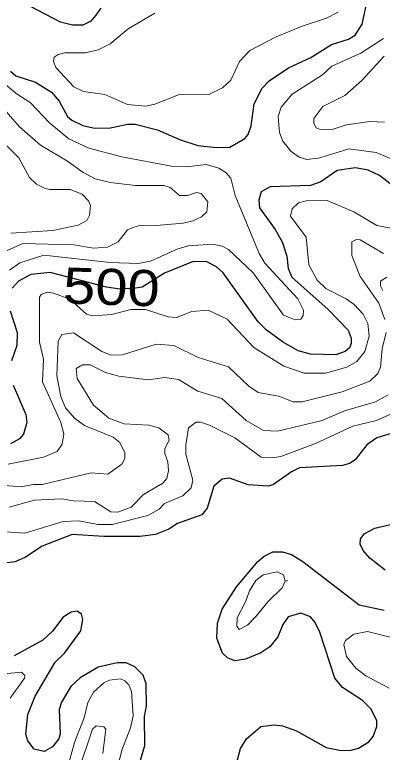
# Model space of a CAD drawing. Extents: x 577 to 602.9, y 7483.8 to 7511.6.
# Drawn here: x 598.664 to 599.479, y 7491.079 to 7492.716 of the extents above; entities that cross this region are included whole.
import ezdxf
from ezdxf.enums import TextEntityAlignment as Align

# ---------------------------------------------------------------- set-up
doc = ezdxf.new("R2010")
doc.units = 0
doc.header["$LTSCALE"] = 0.032
doc.layers.add('1', color=7, linetype='Continuous', lineweight=25)
doc.layers.add('2', color=7, linetype='Continuous', lineweight=13)
doc.layers.add('61', color=7, linetype='Continuous')

msp = doc.modelspace()

# ---------------------------------------------------------------- linework, layer by layer
at = {"layer": '1'}
for points in [[(598.6545, 7492.5903), (598.6664, 7492.58), (598.7102, 7492.5657), (598.7459, 7492.5434), (598.7626, 7492.5235), (598.7809, 7492.4901), (598.7905, 7492.4814), (598.8151, 7492.4695), (598.8382, 7492.4647), (598.8724, 7492.4639), (598.9145, 7492.4726), (598.9312, 7492.4726), (598.9805, 7492.4599), (599.0298, 7492.4384), (599.0704, 7492.4257), (599.1109, 7492.421), (599.1411, 7492.4217), (599.1745, 7492.4408), (599.1817, 7492.4496), (599.1888, 7492.4687), (599.1952, 7492.518), (599.2127, 7492.553), (599.2286, 7492.5689), (599.2715, 7492.5975), (599.3208, 7492.6205), (599.367, 7492.6492), (599.4043, 7492.6611), (599.4194, 7492.6706), (599.4346, 7492.6945), (599.4473, 7492.7533)], [(598.8549, 7492.7303), (598.8437, 7492.7144), (598.8326, 7492.7016), (598.8151, 7492.6921), (598.7921, 7492.6921), (598.7658, 7492.6993), (598.699, 7492.7335)], [(599.4735, 7492.3589), (599.4481, 7492.3709), (599.4202, 7492.3756), (599.3797, 7492.3701), (599.3431, 7492.3446), (599.3201, 7492.3367), (599.231, 7492.3335), (599.2111, 7492.3223), (599.2055, 7492.3041), (599.2071, 7492.2874), (599.2421, 7492.2389), (599.2572, 7492.2118), (599.2676, 7492.18), (599.2707, 7492.1522), (599.2787, 7492.1331), (599.3598, 7492.0615), (599.4035, 7492.0154), (599.4107, 7491.9979), (599.4107, 7491.986), (599.4067, 7491.9764), (599.3972, 7491.9685), (599.3765, 7491.9613), (599.3201, 7491.9621), (599.293, 7491.9701), (599.258, 7491.99), (599.2222, 7492.0162), (599.204, 7492.0345), (599.1268, 7492.1426), (599.1117, 7492.1562), (599.0902, 7492.1673), (599.06, 7492.1681), (598.9964, 7492.1418), (598.9469, 7492.1111), (598.9323, 7492.1088), (598.8972, 7492.1065), (598.8679, 7492.1112), (598.7428, 7492.1434), (598.6998, 7492.1395), (598.672, 7492.1244), (598.6585, 7492.1092)], [(599.5316, 7492.3136), (599.4735, 7492.3589)], [(598.6537, 7492.0584), (598.6696, 7492.0106), (598.6688, 7491.982), (598.6569, 7491.9478)], [(598.6608, 7491.8937), (598.6887, 7491.8285), (598.6911, 7491.8111), (598.6831, 7491.7848), (598.6744, 7491.7745), (598.6545, 7491.7633)], [(599.6254, 7491.8246), (599.4672, 7491.7769), (599.4449, 7491.761), (599.4194, 7491.7276), (599.4067, 7491.7196), (599.3916, 7491.7156), (599.2962, 7491.7101), (599.2779, 7491.7013), (599.2381, 7491.6735), (599.2262, 7491.6695), (599.1817, 7491.6727), (599.1403, 7491.687), (599.1244, 7491.6854), (599.1061, 7491.6695), (599.091, 7491.621), (599.0791, 7491.6059), (599.025, 7491.5868), (599.006, 7491.5741), (598.9765, 7491.5622), (598.9415, 7491.5582), (598.862, 7491.5582), (598.7913, 7491.5622), (598.7245, 7491.5367), (598.6879, 7491.5121), (598.6648, 7491.5017), (598.6402, 7491.4985)], [(599.4862, 7491.4834), (599.452, 7491.5097), (599.4369, 7491.5264), (599.4306, 7491.5407), (599.4314, 7491.5518), (599.4393, 7491.5638), (599.4632, 7491.5765), (599.5196, 7491.59)], [(599.3201, 7491.3793), (599.2986, 7491.388), (599.2707, 7491.3793), (599.2588, 7491.3626), (599.2477, 7491.3355), (599.2302, 7491.3133), (599.2103, 7491.2998), (599.1761, 7491.2854), (599.1523, 7491.2823), (599.1364, 7491.2886), (599.1252, 7491.299), (599.1125, 7491.3324), (599.1141, 7491.3658), (599.1244, 7491.3968), (599.1562, 7491.4461), (599.2032, 7491.5025), (599.2175, 7491.5145), (599.2366, 7491.524), (599.258, 7491.524), (599.2779, 7491.5176), (599.3034, 7491.5025), (599.4282, 7491.4063), (599.4839, 7491.3944)], [(598.9344, 7491.031), (598.9527, 7491.0938), (598.9519, 7491.1582), (598.9567, 7491.1821), (598.9559, 7491.2306), (598.9487, 7491.2505), (598.9304, 7491.2687), (598.9113, 7491.2775), (598.8915, 7491.2775), (598.8493, 7491.2679), (598.8095, 7491.2441), (598.7881, 7491.225), (598.7674, 7491.19), (598.7626, 7491.1741), (598.765, 7491.12), (598.7618, 7491.1089), (598.7475, 7491.0914), (598.7292, 7491.0811), (598.707, 7491.0859), (598.6927, 7491.1041), (598.6887, 7491.1192), (598.6927, 7491.163), (598.7094, 7491.2035), (598.7539, 7491.2791), (598.7746, 7491.299), (598.8103, 7491.3483), (598.8151, 7491.3737), (598.8119, 7491.3856), (598.8024, 7491.392), (598.7889, 7491.3896), (598.7714, 7491.3785), (598.7475, 7491.3475), (598.7261, 7491.3276), (598.6624, 7491.2934)], [(599.1586, 7491.062), (599.165, 7491.0874), (599.1785, 7491.1089), (599.2103, 7491.1359), (599.2397, 7491.1399), (599.258, 7491.1375), (599.289, 7491.1264), (599.355, 7491.0898), (599.3884, 7491.0827), (599.4107, 7491.0835), (599.4266, 7491.0882), (599.4497, 7491.1025), (599.4592, 7491.1137), (599.4672, 7491.1359), (599.4672, 7491.1495), (599.4544, 7491.1757), (599.4354, 7491.194), (599.3916, 7491.2226), (599.3741, 7491.2433), (599.3407, 7491.3459), (599.3304, 7491.3673), (599.3201, 7491.3793)]]:
    msp.add_lwpolyline(points, dxfattribs=at)
at = {"layer": '2'}
for points in [[(598.9749, 7492.7191), (598.9153, 7492.6842), (598.8755, 7492.6508), (598.8493, 7492.638), (598.8199, 7492.6309), (598.7754, 7492.6309), (598.7602, 7492.6277), (598.7515, 7492.6213), (598.7499, 7492.6118), (598.7555, 7492.5983), (598.7952, 7492.5553), (598.8167, 7492.545), (598.8636, 7492.5386), (598.9145, 7492.5164), (598.9543, 7492.5124), (598.9749, 7492.5172), (599.0274, 7492.5378), (599.095, 7492.5386), (599.1252, 7492.5537), (599.1435, 7492.5704), (599.1626, 7492.6118), (599.1857, 7492.6364), (599.2437, 7492.6667), (599.3018, 7492.6905), (599.3558, 7492.708), (599.3813, 7492.7215)], [(599.4823, 7492.6627), (599.4322, 7492.6301), (599.3678, 7492.6015), (599.3471, 7492.5824), (599.2795, 7492.5394), (599.2548, 7492.5108), (599.2485, 7492.4901), (599.2517, 7492.4543), (599.2588, 7492.4353), (599.2763, 7492.413), (599.2954, 7492.3995), (599.3121, 7492.3947), (599.3383, 7492.3971), (599.3582, 7492.4035), (599.4051, 7492.4178), (599.4656, 7492.4098), (599.5149, 7492.3891)], [(599.4839, 7492.6237), (599.4338, 7492.5696), (599.3964, 7492.5363), (599.3479, 7492.5116), (599.328, 7492.4854), (599.328, 7492.4742), (599.3328, 7492.4647), (599.3439, 7492.4599), (599.3686, 7492.4607), (599.4004, 7492.471), (599.452, 7492.479), (599.4847, 7492.4774)], [(598.6338, 7492.1864), (598.6823, 7492.2078), (598.7952, 7492.2047), (598.839, 7492.1975), (598.87, 7492.1999), (598.8938, 7492.2118), (598.9145, 7492.2381), (598.928, 7492.2444), (598.9439, 7492.2484), (598.9781, 7492.2476), (599.0378, 7492.2532), (599.0592, 7492.2579), (599.0783, 7492.2675), (599.0902, 7492.2786), (599.0926, 7492.3001), (599.0775, 7492.3192), (599.0672, 7492.3208), (599.0473, 7492.3144), (599.0298, 7492.3144), (599.0091, 7492.3319), (598.9948, 7492.3367), (598.9312, 7492.3367), (598.8763, 7492.343), (598.8421, 7492.3518), (598.8159, 7492.3653), (598.7809, 7492.3907), (598.7213, 7492.4265), (598.6744, 7492.4671), (598.5988, 7492.553)], [(598.6386, 7492.5649), (598.6672, 7492.541), (598.6982, 7492.5211), (598.742, 7492.475), (598.7841, 7492.44), (598.8286, 7492.4194), (598.9018, 7492.4003), (599.0115, 7492.3796), (599.0449, 7492.378), (599.0887, 7492.3836), (599.1165, 7492.3748), (599.1324, 7492.3653), (599.1435, 7492.3526), (599.1531, 7492.3144), (599.2063, 7492.1856), (599.2191, 7492.1641), (599.2922, 7492.0854)], [(598.6362, 7492.4353), (598.6728, 7492.3979), (598.6966, 7492.3542), (598.7125, 7492.3398), (598.73, 7492.3311), (598.742, 7492.3279), (598.7873, 7492.3279), (598.8135, 7492.3176), (598.8278, 7492.3025), (598.8318, 7492.2921), (598.8302, 7492.2707), (598.8239, 7492.2587), (598.8048, 7492.2484), (598.7483, 7492.2365), (598.6553, 7492.2309)], [(599.4982, 7492.242), (599.4672, 7492.2476), (599.4163, 7492.2786), (599.3574, 7492.3033), (599.3105, 7492.3025), (599.2938, 7492.2985), (599.2795, 7492.285), (599.2755, 7492.2683), (599.3105, 7492.2222), (599.3169, 7492.1609), (599.3352, 7492.1267), (599.3542, 7492.1084), (599.3996, 7492.0854), (599.4171, 7492.0727), (599.4369, 7492.0512), (599.4473, 7492.0305)], [(599.4854, 7492.0393), (599.4719, 7492.0758), (599.4306, 7492.1347), (599.4123, 7492.1816), (599.4123, 7492.2118), (599.4226, 7492.2166), (599.4306, 7492.2158), (599.4823, 7492.1856)], [(599.2922, 7492.0854), (599.3049, 7492.0599), (599.3041, 7492.048), (599.2986, 7492.0401), (599.2859, 7492.0385), (599.2604, 7492.0488), (599.1928, 7492.1426), (599.138, 7492.1943), (599.1244, 7492.2023), (599.1038, 7492.2063), (599.0497, 7492.2031), (599.0258, 7492.1959), (598.9654, 7492.1689), (598.9376, 7492.1633), (598.8748, 7492.1657), (598.7284, 7492.1824), (598.6752, 7492.1649), (598.6521, 7492.149)], [(599.4894, 7492.1331), (599.4759, 7492.1244), (599.4759, 7492.114), (599.4807, 7492.1037)], [(599.4473, 7492.0305), (599.4505, 7492.0027), (599.4409, 7491.9685), (599.4234, 7491.9462), (599.4012, 7491.9335), (599.3534, 7491.92), (599.3065, 7491.92), (599.2612, 7491.9359), (599.1944, 7491.9772), (599.1356, 7492.0401), (599.0934, 7492.0599), (599.0568, 7492.0568), (599.0227, 7492.044), (599.0044, 7492.0456), (598.9543, 7492.0615), (598.9217, 7492.0615), (598.8795, 7492.0504), (598.8366, 7492.0472), (598.8231, 7492.0512), (598.7865, 7492.0846), (598.7499, 7492.0981), (598.7356, 7492.0997), (598.7229, 7492.0949), (598.7189, 7492.0886), (598.7189, 7491.9892), (598.7276, 7491.951), (598.7253, 7491.9009), (598.7666, 7491.8111), (598.773, 7491.7856), (598.769, 7491.7625), (598.7579, 7491.7466), (598.7276, 7491.7339), (598.6497, 7491.718)], [(598.5225, 7491.6806), (598.6783, 7491.6679), (598.7046, 7491.6735), (598.7245, 7491.6735), (598.8334, 7491.6989), (598.8708, 7491.6958), (598.9018, 7491.718), (598.9081, 7491.7307), (598.9081, 7491.7435), (598.897, 7491.7665), (598.8827, 7491.7784), (598.8191, 7491.8039), (598.7968, 7491.8206), (598.7769, 7491.8437), (598.7666, 7491.8683), (598.7571, 7491.9144), (598.7602, 7491.9916), (598.7682, 7492.0059), (598.7944, 7492.0098), (598.8573, 7491.9685), (598.8779, 7491.9605), (598.9034, 7491.9613), (598.9781, 7491.9844), (599.0171, 7491.982), (599.0712, 7491.955), (599.138, 7491.9343), (599.1833, 7491.8914), (599.204, 7491.8771), (599.2501, 7491.8691), (599.2819, 7491.8564), (599.3018, 7491.8564), (599.3908, 7491.8786), (599.452, 7491.9025), (599.4695, 7491.9192), (599.4759, 7491.9335), (599.4791, 7491.9741), (599.4878, 7492.0106)], [(599.4926, 7491.8723), (599.4648, 7491.8564), (599.3956, 7491.8365), (599.3463, 7491.815), (599.2469, 7491.7912), (599.2159, 7491.7928), (599.1777, 7491.815), (599.1236, 7491.8643), (599.0704, 7491.8802), (599.0274, 7491.9065), (598.9964, 7491.9104), (598.9598, 7491.9057), (598.8946, 7491.9136), (598.8652, 7491.9216), (598.831, 7491.9391), (598.8143, 7491.9391), (598.8, 7491.9303), (598.8024, 7491.9081), (598.839, 7491.8492), (598.8724, 7491.8206), (598.9066, 7491.8079), (598.9614, 7491.8047), (598.9837, 7491.7991), (599.0044, 7491.7832), (599.0068, 7491.7713), (598.9972, 7491.753), (598.9972, 7491.7419), (599.0036, 7491.7236), (599.0052, 7491.7037), (599.0012, 7491.6862), (598.9924, 7491.6759), (598.9495, 7491.6512), (598.9225, 7491.6226), (598.893, 7491.6115), (598.8771, 7491.6123), (598.8406, 7491.6353), (598.7944, 7491.6369), (598.7682, 7491.6417), (598.7078, 7491.6385), (598.6513, 7491.6226)], [(599.5093, 7491.8341), (599.4664, 7491.815), (599.4139, 7491.8023), (599.3312, 7491.7641), (599.2541, 7491.7355), (599.2366, 7491.7323), (599.2111, 7491.7339), (599.1523, 7491.7769), (599.0958, 7491.8047), (599.0759, 7491.8118), (599.0664, 7491.8118), (599.0497, 7491.7991), (599.0433, 7491.761), (599.0433, 7491.7403), (599.0592, 7491.683), (599.0553, 7491.6655), (599.037, 7491.648), (598.9964, 7491.6313), (598.9845, 7491.6186), (598.959, 7491.6043), (598.8803, 7491.5844), (598.8485, 7491.5844), (598.8064, 7491.5924), (598.7714, 7491.5908), (598.6863, 7491.5653), (598.6442, 7491.5685)], [(599.2643, 7491.4585), (599.27, 7491.4604), (599.2643, 7491.4585)], [(599.495, 7491.221), (599.4433, 7491.2489), (599.421, 7491.2656), (599.4004, 7491.2918), (599.394, 7491.318), (599.398, 7491.3268), (599.4163, 7491.3411), (599.4465, 7491.3467), (599.5061, 7491.3324)], [(598.6537, 7491.1988), (598.6855, 7491.2433), (598.6863, 7491.2497), (598.6791, 7491.2568), (598.641, 7491.2528)], [(598.8604, 7490.9165), (598.9018, 7491.0835), (598.9209, 7491.1336), (598.9264, 7491.1598), (598.9233, 7491.2139), (598.9169, 7491.229), (598.9081, 7491.2377), (598.8986, 7491.2417), (598.874, 7491.2393), (598.862, 7491.233), (598.839, 7491.2123), (598.8262, 7491.1892), (598.8183, 7491.1558), (598.7976, 7491.1033), (598.7801, 7491.0421)], [(598.8596, 7491.0763), (598.866, 7491.1304), (598.862, 7491.1352), (598.8445, 7491.1375), (598.8366, 7491.1304), (598.8056, 7491.0381)]]:
    msp.add_lwpolyline(points, dxfattribs=at)
msp.add_lwpolyline([(599.2643, 7491.4585), (599.2572, 7491.4437), (599.2254, 7491.4127), (599.2, 7491.3809), (599.1801, 7491.361), (599.1618, 7491.3514), (599.157, 7491.3586), (599.1578, 7491.3777), (599.1769, 7491.4143), (599.1849, 7491.4373), (599.1992, 7491.4604), (599.2151, 7491.4731), (599.2461, 7491.4795), (599.2604, 7491.4731)], close=True, dxfattribs=at)

# ---------------------------------------------------------------- texts
at = {"layer": '61', "width": 1.2}
msp.add_text('500', height=0.08, rotation=358.077, dxfattribs=at).set_placement((598.8773, 7492.0716), align=Align.CENTER)

doc.saveas('drawing.dxf')
